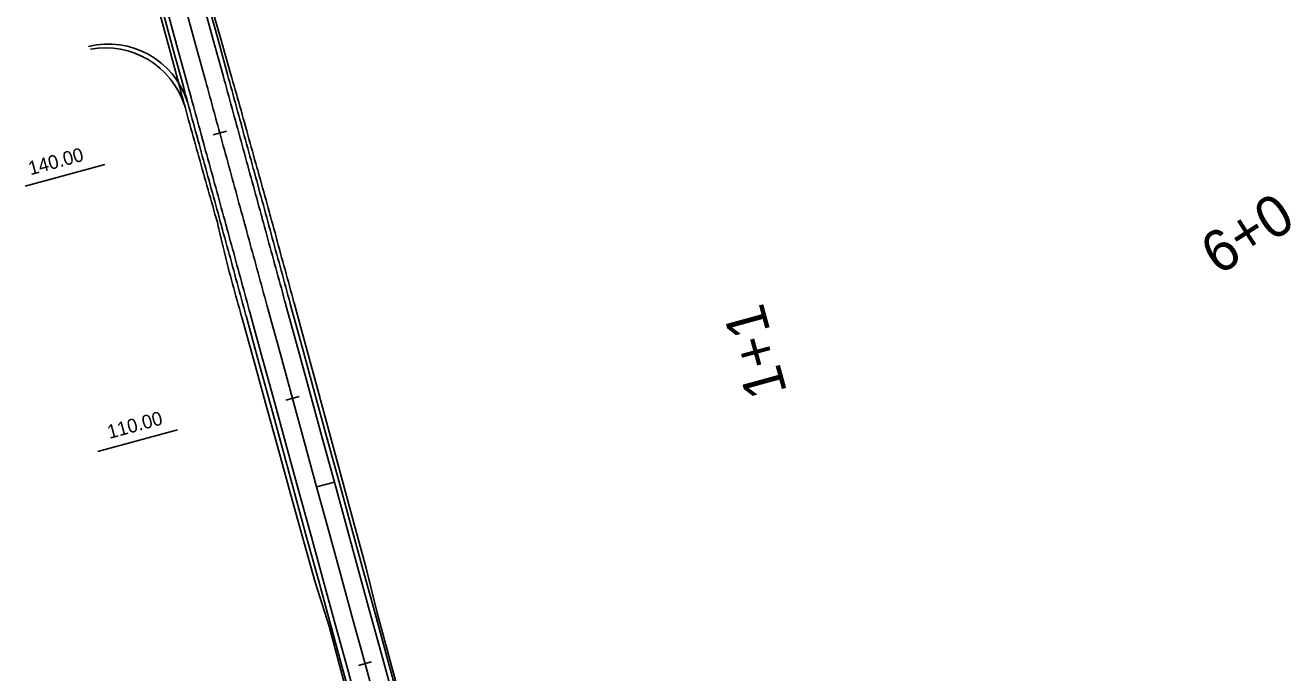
# Model space of a CAD drawing. Extents: x -550605 to -538780, y -1102367 to -1093705.
# Drawn here: x -547360 to -547222, y -1101168.4 to -1101097.8 of the extents above; entities that cross this region are included whole.
import ezdxf

# ---------------------------------------------------------------- set-up
doc = ezdxf.new("R2010")
doc.units = 0
for name, color, linetype in [('SIT - hrany vozovky', 7, 'Continuous'), ('SIT - oblouky - hrany', 7, 'Continuous'), ('SIT - oblouky - koruna', 7, 'Continuous'), ('SIT - osa cesty', 7, 'Continuous'), ('SIT - paty násypů', 7, 'Continuous'), ('SIT - staničení po 100m', 7, 'Continuous'), ('SIT - staničení po 30m', 7, 'Continuous')]:
    doc.layers.add(name, color=color, linetype=linetype)

msp = doc.modelspace()

# ---------------------------------------------------------------- linework, layer by layer
at = {"layer": 'SIT - hrany vozovky'}
for points in [[(-547319.73, -1101171.72), (-547321.05, -1101166.9), (-547322.37, -1101162.07), (-547323.69, -1101157.25), (-547325.01, -1101152.43), (-547326.33, -1101147.61), (-547327.65, -1101142.78), (-547328.97, -1101137.96), (-547330.29, -1101133.14), (-547331.61, -1101128.32), (-547331.63, -1101128.26), (-547331.75, -1101127.81), (-547331.87, -1101127.37), (-547331.99, -1101126.92), (-547332.11, -1101126.48), (-547332.24, -1101126.03), (-547332.36, -1101125.59), (-547332.48, -1101125.14), (-547332.6, -1101124.69), (-547332.72, -1101124.25), (-547332.85, -1101123.8), (-547332.93, -1101123.49), (-547332.97, -1101123.36), (-547333.09, -1101122.91), (-547333.21, -1101122.46), (-547333.33, -1101122.02), (-547333.46, -1101121.57), (-547333.58, -1101121.13), (-547333.7, -1101120.68), (-547333.82, -1101120.24), (-547333.94, -1101119.79), (-547334.07, -1101119.34), (-547334.19, -1101118.9), (-547334.25, -1101118.67), (-547334.31, -1101118.45), (-547334.43, -1101118.01), (-547334.55, -1101117.56), (-547334.68, -1101117.11), (-547334.8, -1101116.67), (-547334.92, -1101116.22), (-547335.04, -1101115.78), (-547335.16, -1101115.33), (-547335.29, -1101114.89), (-547335.41, -1101114.44), (-547335.53, -1101113.99), (-547335.57, -1101113.85), (-547335.65, -1101113.55), (-547335.77, -1101113.1), (-547335.9, -1101112.66), (-547336.02, -1101112.21), (-547336.14, -1101111.76), (-547336.26, -1101111.32), (-547336.39, -1101110.87), (-547336.51, -1101110.43), (-547336.63, -1101109.98), (-547336.75, -1101109.54), (-547336.87, -1101109.09), (-547336.89, -1101109.03), (-547337, -1101108.64), (-547337.12, -1101108.2), (-547337.24, -1101107.75), (-547337.36, -1101107.31), (-547337.48, -1101106.86), (-547337.61, -1101106.41), (-547337.73, -1101105.97), (-547337.85, -1101105.52), (-547337.97, -1101105.08), (-547338.09, -1101104.63), (-547338.21, -1101104.2), (-547338.22, -1101104.19), (-547338.34, -1101103.74), (-547338.46, -1101103.29), (-547339.53, -1101099.38), (-547340.85, -1101094.56)], [(-547319.25, -1101171.59), (-547320.57, -1101166.77), (-547321.89, -1101161.94), (-547323.21, -1101157.12), (-547324.53, -1101152.3), (-547325.85, -1101147.47), (-547327.17, -1101142.65), (-547328.49, -1101137.83), (-547329.81, -1101133.01), (-547331.13, -1101128.18), (-547331.14, -1101128.13), (-547331.27, -1101127.68), (-547331.39, -1101127.24), (-547331.51, -1101126.79), (-547331.63, -1101126.35), (-547331.75, -1101125.9), (-547331.88, -1101125.45), (-547332, -1101125.01), (-547332.12, -1101124.56), (-547332.24, -1101124.12), (-547332.36, -1101123.67), (-547332.45, -1101123.36), (-547332.49, -1101123.22), (-547332.61, -1101122.78), (-547332.73, -1101122.33), (-547332.85, -1101121.89), (-547332.97, -1101121.44), (-547333.1, -1101121), (-547333.22, -1101120.55), (-547333.34, -1101120.1), (-547333.46, -1101119.66), (-547333.58, -1101119.21), (-547333.71, -1101118.77), (-547333.77, -1101118.54), (-547333.83, -1101118.32), (-547333.95, -1101117.87), (-547334.07, -1101117.43), (-547334.19, -1101116.98), (-547334.32, -1101116.54), (-547334.44, -1101116.09), (-547334.56, -1101115.65), (-547334.68, -1101115.2), (-547334.8, -1101114.75), (-547334.93, -1101114.31), (-547335.05, -1101113.86), (-547335.09, -1101113.72), (-547335.17, -1101113.42), (-547335.29, -1101112.97), (-547335.41, -1101112.52), (-547335.54, -1101112.08), (-547335.66, -1101111.63), (-547335.78, -1101111.19), (-547335.9, -1101110.74), (-547336.02, -1101110.3), (-547336.15, -1101109.85), (-547336.27, -1101109.4), (-547336.39, -1101108.96), (-547336.41, -1101108.89), (-547336.51, -1101108.51), (-547336.63, -1101108.07), (-547336.76, -1101107.62), (-547336.88, -1101107.17), (-547337, -1101106.73), (-547337.12, -1101106.28), (-547337.25, -1101105.84), (-547337.37, -1101105.39), (-547337.49, -1101104.95), (-547337.61, -1101104.5), (-547337.73, -1101104.07), (-547337.73, -1101104.05), (-547337.86, -1101103.61), (-547337.98, -1101103.16), (-547339.05, -1101099.25), (-547340.37, -1101094.43)], [(-547324.07, -1101172.91), (-547325.39, -1101168.09), (-547326.71, -1101163.26), (-547328.03, -1101158.44), (-547329.35, -1101153.62), (-547330.67, -1101148.79), (-547331.99, -1101143.97), (-547333.31, -1101139.15), (-547334.63, -1101134.33), (-547335.95, -1101129.5), (-547335.97, -1101129.45), (-547336.09, -1101129), (-547336.21, -1101128.56), (-547336.33, -1101128.11), (-547336.45, -1101127.67), (-547336.58, -1101127.22), (-547336.7, -1101126.77), (-547336.82, -1101126.33), (-547336.94, -1101125.88), (-547337.06, -1101125.44), (-547337.19, -1101124.99), (-547337.27, -1101124.68), (-547337.31, -1101124.54), (-547337.43, -1101124.1), (-547337.55, -1101123.65), (-547337.67, -1101123.21), (-547337.8, -1101122.76), (-547337.92, -1101122.32), (-547338.04, -1101121.87), (-547338.16, -1101121.42), (-547338.28, -1101120.98), (-547338.41, -1101120.53), (-547338.53, -1101120.09), (-547338.59, -1101119.86), (-547338.65, -1101119.64), (-547338.77, -1101119.19), (-547338.9, -1101118.75), (-547339.02, -1101118.3), (-547339.14, -1101117.86), (-547339.26, -1101117.41), (-547339.38, -1101116.97), (-547339.51, -1101116.52), (-547339.63, -1101116.07), (-547339.75, -1101115.63), (-547339.87, -1101115.18), (-547339.91, -1101115.04), (-547339.99, -1101114.74), (-547340.12, -1101114.29), (-547340.24, -1101113.84), (-547340.36, -1101113.4), (-547340.48, -1101112.95), (-547340.6, -1101112.51), (-547340.73, -1101112.06), (-547340.85, -1101111.62), (-547340.97, -1101111.17), (-547341.09, -1101110.72), (-547341.21, -1101110.28), (-547341.23, -1101110.21), (-547341.34, -1101109.83), (-547341.46, -1101109.39), (-547341.58, -1101108.94), (-547341.7, -1101108.49), (-547341.82, -1101108.05), (-547341.95, -1101107.6), (-547342.07, -1101107.16), (-547342.19, -1101106.71), (-547342.31, -1101106.27), (-547342.43, -1101105.82), (-547342.55, -1101105.39), (-547342.56, -1101105.37), (-547342.68, -1101104.93), (-547342.8, -1101104.48), (-547343.87, -1101100.57), (-547345.19, -1101095.75)], [(-547323.59, -1101172.78), (-547324.91, -1101167.95), (-547326.23, -1101163.13), (-547327.55, -1101158.31), (-547328.87, -1101153.49), (-547330.19, -1101148.66), (-547331.51, -1101143.84), (-547332.83, -1101139.02), (-547334.15, -1101134.19), (-547335.47, -1101129.37), (-547335.48, -1101129.32), (-547335.61, -1101128.87), (-547335.73, -1101128.43), (-547335.85, -1101127.98), (-547335.97, -1101127.53), (-547336.09, -1101127.09), (-547336.22, -1101126.64), (-547336.34, -1101126.2), (-547336.46, -1101125.75), (-547336.58, -1101125.3), (-547336.7, -1101124.86), (-547336.79, -1101124.55), (-547336.83, -1101124.41), (-547336.95, -1101123.97), (-547337.07, -1101123.52), (-547337.19, -1101123.08), (-547337.31, -1101122.63), (-547337.44, -1101122.18), (-547337.56, -1101121.74), (-547337.68, -1101121.29), (-547337.8, -1101120.85), (-547337.92, -1101120.4), (-547338.05, -1101119.95), (-547338.11, -1101119.73), (-547338.17, -1101119.51), (-547338.29, -1101119.06), (-547338.41, -1101118.62), (-547338.53, -1101118.17), (-547338.66, -1101117.72), (-547338.78, -1101117.28), (-547338.9, -1101116.83), (-547339.02, -1101116.39), (-547339.14, -1101115.94), (-547339.27, -1101115.5), (-547339.39, -1101115.05), (-547339.43, -1101114.9), (-547339.51, -1101114.6), (-547339.63, -1101114.16), (-547339.76, -1101113.71), (-547339.88, -1101113.27), (-547340, -1101112.82), (-547340.12, -1101112.37), (-547340.24, -1101111.93), (-547340.37, -1101111.48), (-547340.49, -1101111.04), (-547340.61, -1101110.59), (-547340.73, -1101110.15), (-547340.75, -1101110.08), (-547340.85, -1101109.7), (-547340.98, -1101109.25), (-547341.1, -1101108.81), (-547341.22, -1101108.36), (-547341.34, -1101107.92), (-547341.46, -1101107.47), (-547341.59, -1101107.02), (-547341.71, -1101106.58), (-547341.83, -1101106.13), (-547341.95, -1101105.69), (-547342.07, -1101105.26), (-547342.07, -1101105.24), (-547342.2, -1101104.8), (-547342.32, -1101104.35), (-547343.39, -1101100.44), (-547344.71, -1101095.61)]]:
    msp.add_lwpolyline(points, dxfattribs=at)
at = {"layer": 'SIT - oblouky - hrany'}
msp.add_arc((-547351.26, -1101109.26), 9, 17.6968, 100.7044, dxfattribs=at)
at = {"layer": 'SIT - oblouky - koruna'}
msp.add_arc((-547350.95, -1101108.85), 9, 17.7666, 104.0758, dxfattribs=at)
at = {"layer": 'SIT - osa cesty'}
msp.add_lwpolyline([(-547321.66, -1101172.25), (-547322.98, -1101167.43), (-547324.3, -1101162.6), (-547325.62, -1101157.78), (-547326.94, -1101152.96), (-547328.26, -1101148.13), (-547329.58, -1101143.31), (-547330.9, -1101138.49), (-547332.22, -1101133.67), (-547333.54, -1101128.84), (-547333.56, -1101128.79), (-547333.68, -1101128.34), (-547333.8, -1101127.9), (-547333.92, -1101127.45), (-547334.04, -1101127.01), (-547334.17, -1101126.56), (-547334.29, -1101126.11), (-547334.41, -1101125.67), (-547334.53, -1101125.22), (-547334.65, -1101124.78), (-547334.78, -1101124.33), (-547334.86, -1101124.02), (-547334.9, -1101123.88), (-547335.02, -1101123.44), (-547335.14, -1101122.99), (-547335.26, -1101122.55), (-547335.39, -1101122.1), (-547335.51, -1101121.66), (-547335.63, -1101121.21), (-547335.75, -1101120.76), (-547335.87, -1101120.32), (-547336, -1101119.87), (-547336.12, -1101119.43), (-547336.18, -1101119.2), (-547336.24, -1101118.98), (-547336.36, -1101118.53), (-547336.48, -1101118.09), (-547336.61, -1101117.64), (-547336.73, -1101117.2), (-547336.85, -1101116.75), (-547336.97, -1101116.31), (-547337.09, -1101115.86), (-547337.22, -1101115.41), (-547337.34, -1101114.97), (-547337.46, -1101114.52), (-547337.5, -1101114.38), (-547337.58, -1101114.08), (-547337.7, -1101113.63), (-547337.83, -1101113.18), (-547337.95, -1101112.74), (-547338.07, -1101112.29), (-547338.19, -1101111.85), (-547338.31, -1101111.4), (-547338.44, -1101110.96), (-547338.56, -1101110.51), (-547338.68, -1101110.06), (-547338.8, -1101109.62), (-547338.82, -1101109.55), (-547338.92, -1101109.17), (-547339.05, -1101108.73), (-547339.17, -1101108.28), (-547339.29, -1101107.83), (-547339.41, -1101107.39), (-547339.53, -1101106.94), (-547339.66, -1101106.5), (-547339.78, -1101106.05), (-547339.9, -1101105.61), (-547340.02, -1101105.16), (-547340.14, -1101104.73), (-547340.14, -1101104.71), (-547340.27, -1101104.27), (-547340.39, -1101103.82), (-547341.46, -1101099.91), (-547342.78, -1101095.09)], dxfattribs=at)
at = {"layer": 'SIT - paty násypů'}
for points in [[(-547319.03, -1101171.53), (-547320.35, -1101166.71), (-547321.65, -1101161.88), (-547322.85, -1101157.02), (-547324.16, -1101152.2), (-547325.47, -1101147.37), (-547326.78, -1101142.55), (-547328.09, -1101137.72), (-547329.41, -1101132.9), (-547330.72, -1101128.07), (-547330.73, -1101128.02), (-547330.85, -1101127.57), (-547330.97, -1101127.12), (-547331.1, -1101126.68), (-547331.22, -1101126.23), (-547331.34, -1101125.79), (-547331.46, -1101125.34), (-547331.59, -1101124.89), (-547331.71, -1101124.45), (-547331.83, -1101124), (-547331.95, -1101123.56), (-547332.04, -1101123.25), (-547332.08, -1101123.11), (-547332.2, -1101122.67), (-547332.32, -1101122.22), (-547332.44, -1101121.77), (-547332.56, -1101121.33), (-547332.68, -1101120.88), (-547332.8, -1101120.44), (-547332.92, -1101119.99), (-547333.05, -1101119.54), (-547333.17, -1101119.1), (-547333.29, -1101118.65), (-547333.35, -1101118.43), (-547333.41, -1101118.21), (-547333.54, -1101117.76), (-547333.66, -1101117.32), (-547333.78, -1101116.87), (-547333.91, -1101116.42), (-547334.03, -1101115.98), (-547334.15, -1101115.53), (-547334.27, -1101115.09), (-547334.4, -1101114.64), (-547334.53, -1101114.2), (-547334.65, -1101113.75), (-547334.69, -1101113.61), (-547334.78, -1101113.31), (-547334.9, -1101112.86), (-547335.03, -1101112.42), (-547335.15, -1101111.97), (-547335.27, -1101111.53), (-547335.4, -1101111.08), (-547335.52, -1101110.64), (-547335.64, -1101110.19), (-547335.77, -1101109.75), (-547335.89, -1101109.3), (-547336.01, -1101108.85), (-547336.03, -1101108.79), (-547336.14, -1101108.41), (-547336.26, -1101107.96), (-547336.39, -1101107.52), (-547336.51, -1101107.07), (-547336.64, -1101106.63), (-547336.76, -1101106.18), (-547336.89, -1101105.74), (-547337.01, -1101105.29), (-547337.14, -1101104.85), (-547337.27, -1101104.4), (-547337.39, -1101103.98), (-547337.39, -1101103.96), (-547337.52, -1101103.52), (-547337.64, -1101103.07), (-547338.76, -1101099.17), (-547340.12, -1101094.36)], [(-547324.3, -1101172.97), (-547325.61, -1101168.14), (-547326.91, -1101163.32), (-547328.43, -1101158.55), (-547329.77, -1101153.73), (-547331.1, -1101148.91), (-547332.43, -1101144.09), (-547333.75, -1101139.27), (-547335.09, -1101134.45), (-547336.43, -1101129.63), (-547336.44, -1101129.58), (-547336.57, -1101129.13), (-547336.69, -1101128.69), (-547336.81, -1101128.24), (-547336.94, -1101127.8), (-547337.06, -1101127.35), (-547337.18, -1101126.91), (-547337.31, -1101126.46), (-547337.43, -1101126.01), (-547337.55, -1101125.57), (-547337.67, -1101125.12), (-547337.76, -1101124.81), (-547337.79, -1101124.68), (-547337.9, -1101124.23), (-547338.01, -1101123.78), (-547338.12, -1101123.33), (-547338.23, -1101122.88), (-547338.34, -1101122.43), (-547338.45, -1101121.98), (-547338.56, -1101121.53), (-547338.66, -1101121.08), (-547338.77, -1101120.63), (-547338.88, -1101120.18), (-547338.93, -1101119.95), (-547338.99, -1101119.73), (-547339.09, -1101119.28), (-547339.22, -1101118.84), (-547339.35, -1101118.39), (-547339.48, -1101117.95), (-547339.6, -1101117.5), (-547339.73, -1101117.06), (-547339.85, -1101116.61), (-547339.98, -1101116.17), (-547340.1, -1101115.73), (-547340.23, -1101115.28), (-547340.27, -1101115.13), (-547340.35, -1101114.84), (-547340.48, -1101114.39), (-547340.6, -1101113.94), (-547340.73, -1101113.5), (-547340.85, -1101113.05), (-547340.98, -1101112.61), (-547341.1, -1101112.16), (-547341.22, -1101111.72), (-547341.35, -1101111.27), (-547341.47, -1101110.83), (-547341.6, -1101110.38), (-547341.61, -1101110.32), (-547341.72, -1101109.94), (-547341.85, -1101109.49), (-547341.97, -1101109.05), (-547342.09, -1101108.6), (-547342.22, -1101108.16), (-547342.34, -1101107.71), (-547342.46, -1101107.26), (-547342.58, -1101106.82), (-547342.71, -1101106.37), (-547342.83, -1101105.93), (-547342.94, -1101105.5), (-547342.95, -1101105.48), (-547343.07, -1101105.03), (-547343.19, -1101104.59), (-547344.25, -1101100.67), (-547345.56, -1101095.85)]]:
    msp.add_lwpolyline(points, dxfattribs=at)
at = {"layer": 'SIT - staničení po 100m'}
msp.add_lwpolyline([(-547328.26, -1101148.13), (-547326.33, -1101147.61)], dxfattribs=at)
at = {"layer": 'SIT - staničení po 30m'}
for points in [[(-547339.54, -1101109.75), (-547338.1, -1101109.36)], [(-547360.04, -1101115.36), (-547351.36, -1101112.99)], [(-547331.62, -1101138.69), (-547330.18, -1101138.29)], [(-547352.12, -1101144.3), (-547343.44, -1101141.92)], [(-547323.7, -1101167.62), (-547322.26, -1101167.23)]]:
    msp.add_lwpolyline(points, dxfattribs=at)

# ---------------------------------------------------------------- texts
at = {"layer": 'SIT - staničení po 100m'}
for s, rotation, p in [('0+9', 212.5198, (-547223.68, -1101115.84)), ('1+1', 105.307, (-547276.92, -1101137.78))]:
    msp.add_text(s, height=4.5, rotation=rotation, dxfattribs=at).set_placement(p)
at = {"layer": 'SIT - staničení po 30m'}
for s, p in [('140.00', (-547359.48, -1101114.17)), ('110.00', (-547350.86, -1101142.92))]:
    msp.add_text(s, height=1.5, rotation=15.307, dxfattribs=at).set_placement(p)

doc.saveas('drawing.dxf')
